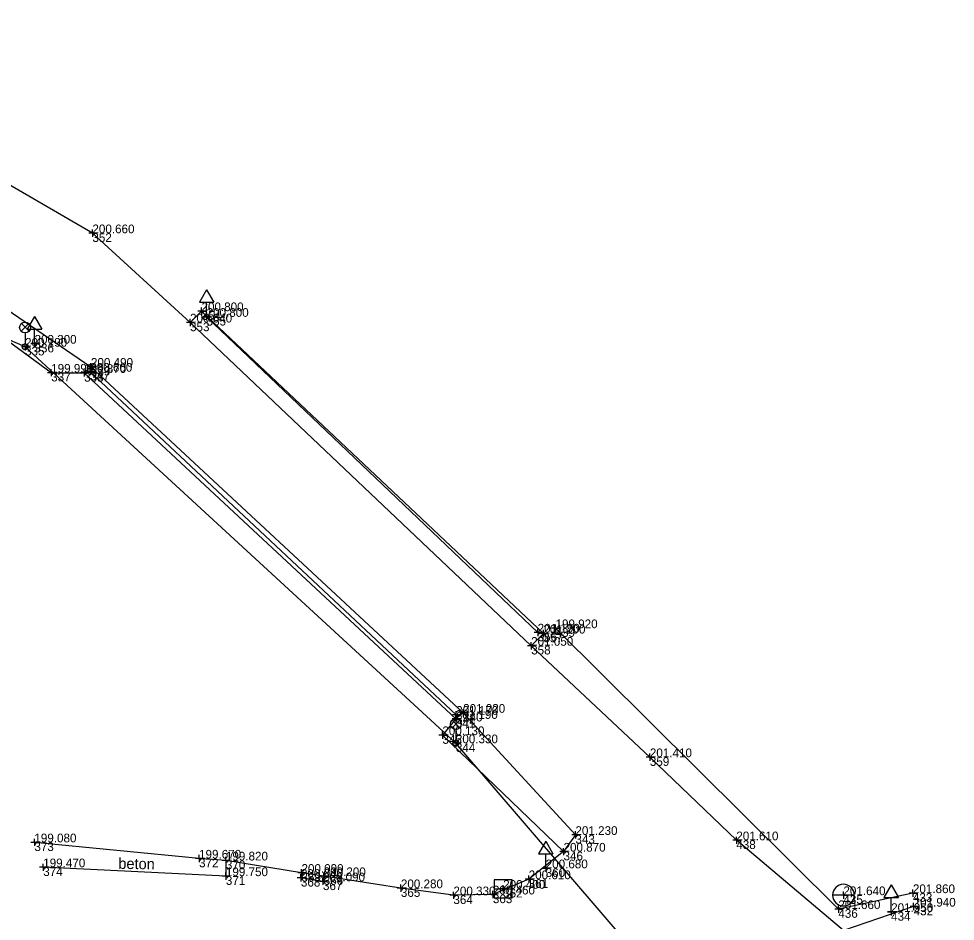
# Model space of a CAD drawing. Extents: x -744883 to -744469, y -966832 to -966374.
# Drawn here: x -744667.9 to -744603.3, y -966691.4 to -966629.2 of the extents above; entities that cross this region are included whole.
import ezdxf

# ---------------------------------------------------------------- set-up
doc = ezdxf.new("R2010")
doc.units = 0
for name, color, linetype in [('Body polohopisu', 7, 'Continuous'), ('Budovy', 7, 'Continuous'), ('Doplňkové značky', 7, 'Continuous'), ('Ploty_opěrné zdi', 7, 'Continuous'), ('Popisy objektů_povrchů', 7, 'Continuous'), ('Rozhraní ploch', 7, 'Continuous'), ('Vrstva 132', 7, 'Continuous'), ('Vstup na pozemek', 7, 'Continuous'), ('Výšky bodů', 7, 'Continuous'), ('Značky IS', 7, 'Continuous'), ('Čísla bodů', 7, 'Continuous')]:
    doc.layers.add(name, color=color, linetype=linetype)

msp = doc.modelspace()

# ---------------------------------------------------------------- linework, layer by layer
at = {"layer": 'Body polohopisu'}
for p, q in [((-744662.8, -966644.01), (-744663.05, -966644.01)), ((-744662.8, -966644.01), (-744662.8, -966643.76)), ((-744662.8, -966644.01), (-744662.55, -966644.01)), ((-744662.8, -966644.01), (-744662.8, -966644.26)), ((-744655.28, -966649.38), (-744655.53, -966649.38)), ((-744655.28, -966649.38), (-744655.28, -966649.13)), ((-744655.28, -966649.38), (-744655.03, -966649.38)), ((-744655.28, -966649.38), (-744655.28, -966649.63)), ((-744656.07, -966650.16), (-744656.07, -966649.91)), ((-744654.93, -966649.77), (-744655.18, -966649.77)), ((-744654.93, -966649.77), (-744654.93, -966649.52)), ((-744654.93, -966649.77), (-744654.68, -966649.77)), ((-744654.93, -966649.77), (-744654.93, -966650.02)), ((-744656.07, -966650.16), (-744656.32, -966650.16)), ((-744656.07, -966650.16), (-744655.82, -966650.16)), ((-744656.07, -966650.16), (-744656.07, -966650.41)), ((-744667.44, -966651.83), (-744667.69, -966651.83)), ((-744667.44, -966651.83), (-744667.44, -966651.58)), ((-744667.44, -966651.83), (-744667.19, -966651.83)), ((-744667.44, -966651.83), (-744667.44, -966652.08)), ((-744666.79, -966651.62), (-744667.04, -966651.62)), ((-744666.79, -966651.62), (-744666.79, -966651.37)), ((-744666.79, -966651.62), (-744666.54, -966651.62)), ((-744666.79, -966651.62), (-744666.79, -966651.87)), ((-744662.9, -966653.21), (-744663.15, -966653.21)), ((-744662.9, -966653.21), (-744662.9, -966652.96)), ((-744662.9, -966653.21), (-744662.65, -966653.21)), ((-744662.9, -966653.21), (-744662.9, -966653.46)), ((-744665.64, -966653.62), (-744665.89, -966653.62)), ((-744665.64, -966653.62), (-744665.64, -966653.37)), ((-744665.64, -966653.62), (-744665.39, -966653.62)), ((-744665.64, -966653.62), (-744665.64, -966653.87)), ((-744663.37, -966653.64), (-744663.62, -966653.64)), ((-744663.37, -966653.64), (-744663.37, -966653.39)), ((-744663.37, -966653.64), (-744663.12, -966653.64)), ((-744663.37, -966653.64), (-744663.37, -966653.89)), ((-744662.95, -966653.55), (-744663.2, -966653.55)), ((-744662.95, -966653.55), (-744662.95, -966653.3)), ((-744662.95, -966653.55), (-744662.7, -966653.55)), ((-744662.95, -966653.55), (-744662.95, -966653.8)), ((-744632.11, -966671.53), (-744632.11, -966671.28)), ((-744630.88, -966671.23), (-744631.13, -966671.23)), ((-744630.88, -966671.23), (-744630.88, -966670.98)), ((-744630.88, -966671.23), (-744630.63, -966671.23)), ((-744630.88, -966671.23), (-744630.88, -966671.48)), ((-744632.11, -966671.53), (-744632.36, -966671.53)), ((-744632.11, -966671.53), (-744631.86, -966671.53)), ((-744632.11, -966671.53), (-744632.11, -966671.78)), ((-744631.72, -966671.6), (-744631.97, -966671.6)), ((-744631.72, -966671.6), (-744631.72, -966671.35)), ((-744631.72, -966671.6), (-744631.47, -966671.6)), ((-744631.72, -966671.6), (-744631.72, -966671.85)), ((-744632.56, -966672.44), (-744632.81, -966672.44)), ((-744632.56, -966672.44), (-744632.56, -966672.19)), ((-744632.56, -966672.44), (-744632.31, -966672.44)), ((-744632.56, -966672.44), (-744632.56, -966672.69)), ((-744637.73, -966677.2), (-744637.73, -966676.95)), ((-744637.25, -966677.06), (-744637.5, -966677.06)), ((-744637.25, -966677.06), (-744637.25, -966676.81)), ((-744637.25, -966677.06), (-744637, -966677.06)), ((-744637.25, -966677.06), (-744637.25, -966677.31)), ((-744637.76, -966677.48), (-744638.01, -966677.48)), ((-744637.73, -966677.2), (-744637.98, -966677.2)), ((-744637.76, -966677.48), (-744637.76, -966677.23)), ((-744637.76, -966677.48), (-744637.51, -966677.48)), ((-744637.76, -966677.48), (-744637.76, -966677.73)), ((-744637.73, -966677.2), (-744637.48, -966677.2)), ((-744637.73, -966677.2), (-744637.73, -966677.45)), ((-744638.68, -966678.6), (-744638.68, -966678.35)), ((-744638.68, -966678.6), (-744638.93, -966678.6)), ((-744638.68, -966678.6), (-744638.43, -966678.6)), ((-744638.68, -966678.6), (-744638.68, -966678.85)), ((-744637.75, -966679.16), (-744637.75, -966678.91)), ((-744637.75, -966679.16), (-744638, -966679.16)), ((-744637.75, -966679.16), (-744637.5, -966679.16)), ((-744637.75, -966679.16), (-744637.75, -966679.41)), ((-744624.38, -966680.12), (-744624.63, -966680.12)), ((-744624.38, -966680.12), (-744624.38, -966679.87)), ((-744624.38, -966680.12), (-744624.13, -966680.12)), ((-744624.38, -966680.12), (-744624.38, -966680.37)), ((-744629.51, -966685.48), (-744629.76, -966685.48)), ((-744629.51, -966685.48), (-744629.51, -966685.23)), ((-744629.51, -966685.48), (-744629.26, -966685.48)), ((-744629.51, -966685.48), (-744629.51, -966685.73)), ((-744666.8, -966685.99), (-744667.05, -966685.99)), ((-744666.8, -966685.99), (-744666.8, -966685.74)), ((-744666.8, -966685.99), (-744666.55, -966685.99)), ((-744666.8, -966685.99), (-744666.8, -966686.24)), ((-744618.42, -966685.85), (-744618.67, -966685.85)), ((-744618.42, -966685.85), (-744618.42, -966685.6)), ((-744618.42, -966685.85), (-744618.17, -966685.85)), ((-744618.42, -966685.85), (-744618.42, -966686.1)), ((-744630.33, -966686.63), (-744630.58, -966686.63)), ((-744630.33, -966686.63), (-744630.33, -966686.38)), ((-744630.33, -966686.63), (-744630.08, -966686.63)), ((-744630.33, -966686.63), (-744630.33, -966686.88)), ((-744666.19, -966687.71), (-744666.19, -966687.46)), ((-744655.45, -966687.11), (-744655.7, -966687.11)), ((-744655.45, -966687.11), (-744655.45, -966686.86)), ((-744655.45, -966687.11), (-744655.2, -966687.11)), ((-744655.45, -966687.11), (-744655.45, -966687.36)), ((-744653.6, -966687.24), (-744653.85, -966687.24)), ((-744653.6, -966687.24), (-744653.6, -966686.99)), ((-744653.6, -966687.24), (-744653.35, -966687.24)), ((-744653.6, -966687.24), (-744653.6, -966687.49)), ((-744666.19, -966687.71), (-744666.44, -966687.71)), ((-744666.19, -966687.71), (-744665.94, -966687.71)), ((-744666.19, -966687.71), (-744666.19, -966687.96)), ((-744653.6, -966688.32), (-744653.6, -966688.07)), ((-744648.39, -966688.09), (-744648.64, -966688.09)), ((-744648.39, -966688.09), (-744648.39, -966687.84)), ((-744648.39, -966688.09), (-744648.14, -966688.09)), ((-744648.39, -966688.09), (-744648.39, -966688.34)), ((-744646.86, -966688.32), (-744646.86, -966688.07)), ((-744631.56, -966687.78), (-744631.81, -966687.78)), ((-744631.56, -966687.78), (-744631.56, -966687.53)), ((-744631.56, -966687.78), (-744631.31, -966687.78)), ((-744631.56, -966687.78), (-744631.56, -966688.03)), ((-744653.6, -966688.32), (-744653.85, -966688.32)), ((-744653.6, -966688.32), (-744653.35, -966688.32)), ((-744653.6, -966688.32), (-744653.6, -966688.57)), ((-744648.43, -966688.44), (-744648.68, -966688.44)), ((-744648.43, -966688.44), (-744648.43, -966688.19)), ((-744648.43, -966688.44), (-744648.18, -966688.44)), ((-744648.43, -966688.44), (-744648.43, -966688.69)), ((-744646.91, -966688.68), (-744647.16, -966688.68)), ((-744646.86, -966688.32), (-744647.11, -966688.32)), ((-744646.91, -966688.68), (-744646.91, -966688.43)), ((-744646.91, -966688.68), (-744646.66, -966688.68)), ((-744646.91, -966688.68), (-744646.91, -966688.93)), ((-744646.86, -966688.32), (-744646.61, -966688.32)), ((-744646.86, -966688.32), (-744646.86, -966688.57)), ((-744632.73, -966688.53), (-744632.98, -966688.53)), ((-744632.73, -966688.53), (-744632.73, -966688.28)), ((-744632.73, -966688.53), (-744632.48, -966688.53)), ((-744632.73, -966688.53), (-744632.73, -966688.78)), ((-744641.54, -966689.15), (-744641.79, -966689.15)), ((-744641.54, -966689.15), (-744641.54, -966688.9)), ((-744641.54, -966689.15), (-744641.29, -966689.15)), ((-744641.54, -966689.15), (-744641.54, -966689.4)), ((-744637.92, -966689.64), (-744637.92, -966689.39)), ((-744635.2, -966689.58), (-744635.2, -966689.33)), ((-744634.49, -966689.19), (-744634.74, -966689.19)), ((-744634.49, -966689.19), (-744634.49, -966688.94)), ((-744634.49, -966689.19), (-744634.24, -966689.19)), ((-744634.49, -966689.19), (-744634.49, -966689.44)), ((-744611.04, -966689.63), (-744611.04, -966689.38)), ((-744606.25, -966689.49), (-744606.25, -966689.24)), ((-744637.92, -966689.64), (-744638.17, -966689.64)), ((-744637.92, -966689.64), (-744637.67, -966689.64)), ((-744637.92, -966689.64), (-744637.92, -966689.89)), ((-744635.2, -966689.58), (-744635.45, -966689.58)), ((-744635.2, -966689.58), (-744634.95, -966689.58)), ((-744635.2, -966689.58), (-744635.2, -966689.83)), ((-744611.04, -966689.63), (-744611.29, -966689.63)), ((-744611.04, -966689.63), (-744610.79, -966689.63)), ((-744611.04, -966689.63), (-744611.04, -966689.88)), ((-744606.25, -966689.49), (-744606.5, -966689.49)), ((-744606.25, -966689.49), (-744606, -966689.49)), ((-744606.25, -966689.49), (-744606.25, -966689.74)), ((-744611.39, -966690.59), (-744611.64, -966690.59)), ((-744611.39, -966690.59), (-744611.39, -966690.34)), ((-744611.39, -966690.59), (-744611.14, -966690.59)), ((-744611.39, -966690.59), (-744611.39, -966690.84)), ((-744607.75, -966690.79), (-744607.75, -966690.54)), ((-744606.2, -966690.42), (-744606.45, -966690.42)), ((-744606.2, -966690.42), (-744606.2, -966690.17)), ((-744606.2, -966690.42), (-744605.95, -966690.42)), ((-744606.2, -966690.42), (-744606.2, -966690.67)), ((-744607.75, -966690.79), (-744608, -966690.79)), ((-744607.75, -966690.79), (-744607.5, -966690.79)), ((-744607.75, -966690.79), (-744607.75, -966691.04))]:
    msp.add_line(p, q, dxfattribs=at)
at = {"layer": 'Budovy'}
msp.add_lwpolyline([(-744641.54, -966689.15), (-744646.86, -966688.32), (-744648.39, -966688.09), (-744653.6, -966687.24)], dxfattribs=at)
at = {"layer": 'Doplňkové značky'}
for p, q in [((-744654.93, -966647.904), (-744655.43, -966648.77)), ((-744654.93, -966647.904), (-744654.43, -966648.77)), ((-744655.43, -966648.77), (-744654.43, -966648.77)), ((-744654.93, -966649.77), (-744654.93, -966648.77)), ((-744666.79, -966649.754), (-744667.29, -966650.62)), ((-744666.79, -966649.754), (-744666.29, -966650.62)), ((-744655.18, -966649.77), (-744654.68, -966649.77)), ((-744667.704, -966650.768), (-744667.176, -966650.24)), ((-744667.168, -966650.765), (-744667.696, -966650.236)), ((-744667.29, -966650.62), (-744666.29, -966650.62)), ((-744666.79, -966651.62), (-744666.79, -966650.62)), ((-744667.44, -966650.88), (-744667.44, -966651.63)), ((-744667.04, -966651.62), (-744666.54, -966651.62)), ((-744638.014, -966678.098), (-744637.486, -966677.57)), ((-744637.478, -966678.095), (-744638.006, -966677.566)), ((-744637.75, -966678.21), (-744637.75, -966678.96)), ((-744631.56, -966685.914), (-744632.06, -966686.78)), ((-744631.56, -966685.914), (-744631.06, -966686.78)), ((-744632.06, -966686.78), (-744631.06, -966686.78)), ((-744631.56, -966687.78), (-744631.56, -966686.78)), ((-744631.81, -966687.78), (-744631.31, -966687.78)), ((-744607.75, -966688.924), (-744608.25, -966689.79)), ((-744607.75, -966688.924), (-744607.25, -966689.79)), ((-744608.25, -966689.79), (-744607.25, -966689.79)), ((-744607.75, -966690.79), (-744607.75, -966689.79)), ((-744608, -966690.79), (-744607.5, -966690.79))]:
    msp.add_line(p, q, dxfattribs=at)
for centre, radius in [((-744667.44, -966650.505), 0.375), ((-744667.44, -966651.83), 0.2), ((-744637.75, -966677.835), 0.375), ((-744637.75, -966679.16), 0.2)]:
    msp.add_circle(centre, radius, dxfattribs=at)
at = {"layer": 'Ploty_opěrné zdi'}
for points in [[(-744665.64, -966653.62), (-744673.1, -966648.16), (-744678.33, -966645.42), (-744681.24, -966644.28)], [(-744654.93, -966649.77), (-744632.11, -966671.53)], [(-744665.64, -966653.62), (-744663.37, -966653.64)], [(-744637.73, -966677.2), (-744662.95, -966653.55)], [(-744606.25, -966689.49), (-744611.39, -966690.59), (-744630.88, -966671.23)], [(-744637.76, -966677.48), (-744638.68, -966678.6), (-744630.33, -966686.63)], [(-744655.45, -966687.11), (-744666.8, -966685.99)], [(-744630.33, -966686.63), (-744632.73, -966688.53), (-744635.2, -966689.58), (-744637.92, -966689.64)]]:
    msp.add_lwpolyline(points, dxfattribs=at)
at = {"layer": 'Rozhraní ploch'}
for points in [[(-744656.07, -966650.16), (-744662.8, -966644.01), (-744672.73, -966638.23), (-744685.11, -966632.67), (-744699.67, -966627.63), (-744718.38, -966621.41), (-744745.96, -966612.84), (-744758.4, -966608.84), (-744770.58, -966603.83), (-744782.97, -966596.56), (-744784.85, -966594.86)], [(-744699.195, -966637.631), (-744690.84, -966638.9), (-744683.64, -966641.84), (-744676.61, -966644.68), (-744670.81, -966647.81), (-744662.9, -966653.21)], [(-744632.56, -966672.44), (-744656.07, -966650.16), (-744655.28, -966649.38), (-744631.72, -966671.6), (-744632.56, -966672.44)], [(-744663.37, -966653.64), (-744662.9, -966653.21), (-744637.25, -966677.06), (-744637.76, -966677.48), (-744663.37, -966653.64)], [(-744606.2, -966690.42), (-744611.03, -966692.07), (-744618.42, -966685.85), (-744624.38, -966680.12), (-744632.56, -966672.44)], [(-744637.25, -966677.06), (-744629.51, -966685.48), (-744630.33, -966686.63)], [(-744653.6, -966687.24), (-744653.6, -966688.32), (-744666.19, -966687.71)], [(-744646.86, -966688.32), (-744646.91, -966688.68), (-744648.43, -966688.44), (-744648.39, -966688.09)]]:
    msp.add_lwpolyline(points, dxfattribs=at)
at = {"layer": 'Vrstva 132'}
msp.add_lwpolyline([(-744622.6, -966696.82), (-744637.75, -966679.16), (-744667.44, -966651.83), (-744705.89, -966635.13)], dxfattribs=at)
at = {"layer": 'Vstup na pozemek'}
for points in [[(-744653.6, -966687.24), (-744655.45, -966687.11)], [(-744637.92, -966689.64), (-744641.54, -966689.15)]]:
    msp.add_lwpolyline(points, dxfattribs=at)
at = {"layer": 'Značky IS'}
for p, q in [((-744635.116, -966689.189), (-744633.866, -966689.189)), ((-744610.292, -966689.63), (-744611.787, -966689.63))]:
    msp.add_line(p, q, dxfattribs=at)
msp.add_lwpolyline([(-744635.116, -966689.817), (-744633.864, -966689.817), (-744633.864, -966688.563), (-744635.116, -966688.563)], close=True, dxfattribs=at)
for start, end in [(0, 180), (180, 0)]:
    msp.add_arc((-744611.04, -966689.63), 0.747, start, end, dxfattribs=at)

# ---------------------------------------------------------------- texts
at = {"layer": 'Popisy objektů_povrchů'}
msp.add_text('beton', height=0.75, rotation=359.07862, dxfattribs=at).set_placement((-744661.017, -966687.815))
at = {"layer": 'Výšky bodů'}
for s, p in [('200.660', (-744662.8, -966644.01)), ('200.800', (-744655.28, -966649.38)), ('200.800', (-744654.93, -966649.77)), ('200.640', (-744656.07, -966650.16)), ('200.190', (-744667.44, -966651.83)), ('200.300', (-744666.79, -966651.62)), ('200.490', (-744662.9, -966653.21)), ('199.990', (-744665.64, -966653.62)), ('199.870', (-744663.37, -966653.64)), ('200.660', (-744662.95, -966653.55)), ('199.920', (-744630.88, -966671.23)), ('201.190', (-744632.11, -966671.53)), ('201.200', (-744631.72, -966671.6)), ('201.050', (-744632.56, -966672.44)), ('201.020', (-744637.25, -966677.06)), ('201.190', (-744637.76, -966677.48)), ('201.170', (-744637.73, -966677.2)), ('200.130', (-744638.68, -966678.6)), ('200.330', (-744637.75, -966679.16)), ('201.410', (-744624.38, -966680.12)), ('201.230', (-744629.51, -966685.48)), ('199.080', (-744666.8, -966685.99)), ('201.610', (-744618.42, -966685.85)), ('200.870', (-744630.33, -966686.63)), ('199.670', (-744655.45, -966687.11)), ('199.820', (-744653.6, -966687.24)), ('199.470', (-744666.19, -966687.71)), ('200.090', (-744648.39, -966688.09)), ('200.680', (-744631.56, -966687.78)), ('199.750', (-744653.6, -966688.32)), ('200.040', (-744648.43, -966688.44)), ('200.090', (-744646.91, -966688.68)), ('200.200', (-744646.86, -966688.32)), ('200.610', (-744632.73, -966688.53)), ('200.280', (-744641.54, -966689.15)), ('200.400', (-744634.49, -966689.19)), ('200.330', (-744637.92, -966689.64)), ('200.460', (-744635.2, -966689.58)), ('201.640', (-744611.04, -966689.63)), ('201.860', (-744606.25, -966689.49)), ('201.660', (-744611.39, -966690.59)), ('201.940', (-744606.2, -966690.42)), ('201.950', (-744607.75, -966690.79))]:
    msp.add_text(s, height=0.6, dxfattribs=at).set_placement(p)
at = {"layer": 'Čísla bodů'}
for s, p in [('352', (-744662.8, -966644.61)), ('354', (-744655.28, -966649.98)), ('355', (-744654.93, -966650.37)), ('353', (-744656.07, -966650.76)), ('335', (-744667.44, -966652.43)), ('336', (-744666.79, -966652.22)), ('339', (-744662.9, -966653.81)), ('337', (-744665.64, -966654.22)), ('338', (-744663.37, -966654.24)), ('347', (-744662.95, -966654.15)), ('439', (-744630.88, -966671.83)), ('356', (-744632.11, -966672.13)), ('357', (-744631.72, -966672.2)), ('358', (-744632.56, -966673.04)), ('340', (-744637.25, -966677.66)), ('341', (-744637.76, -966678.08)), ('342', (-744637.73, -966677.8)), ('345', (-744638.68, -966679.2)), ('344', (-744637.75, -966679.76)), ('359', (-744624.38, -966680.72)), ('343', (-744629.51, -966686.08)), ('373', (-744666.8, -966686.59)), ('438', (-744618.42, -966686.45)), ('346', (-744630.33, -966687.23)), ('372', (-744655.45, -966687.71)), ('370', (-744653.6, -966687.84)), ('374', (-744666.19, -966688.31)), ('369', (-744648.39, -966688.69)), ('360', (-744631.56, -966688.38)), ('371', (-744653.6, -966688.92)), ('368', (-744648.43, -966689.04)), ('367', (-744646.91, -966689.28)), ('366', (-744646.86, -966688.92)), ('361', (-744632.73, -966689.13)), ('365', (-744641.54, -966689.75)), ('362', (-744634.49, -966689.79)), ('364', (-744637.92, -966690.24)), ('363', (-744635.2, -966690.18)), ('435', (-744611.04, -966690.23)), ('433', (-744606.25, -966690.09)), ('436', (-744611.39, -966691.19)), ('432', (-744606.2, -966691.02)), ('434', (-744607.75, -966691.39))]:
    msp.add_text(s, height=0.6, dxfattribs=at).set_placement(p)

doc.saveas('drawing.dxf')
